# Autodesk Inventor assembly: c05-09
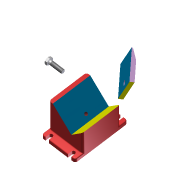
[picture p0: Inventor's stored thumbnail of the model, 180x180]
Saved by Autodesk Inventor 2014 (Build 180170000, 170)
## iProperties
Created: 2010-11
Part Number: c05-09
Document SubType Name: Assembly
Designer: Thom Tremblay
Author: Thom Tremblay
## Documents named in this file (4)
- C:\Inventor 2014 Essentials\Assemblies\Chapter 05\c05-09.iam
- C:\Inventor 2014 Essentials\Content Center Files\en-US\ISO 4017\ISO 4017 - M10 x 35ISO.ipt
- C:\Inventor 2014 Essentials\Parts\Chapter 05\c05-09.ipt
- C:\Inventor 2014 Essentials\Parts\Chapter 05\c05-10.ipt
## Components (3 placed, 3 different names)
1. c05-09:1
2. c05-10:1
3. ISO 4017 M10 x 35:1
